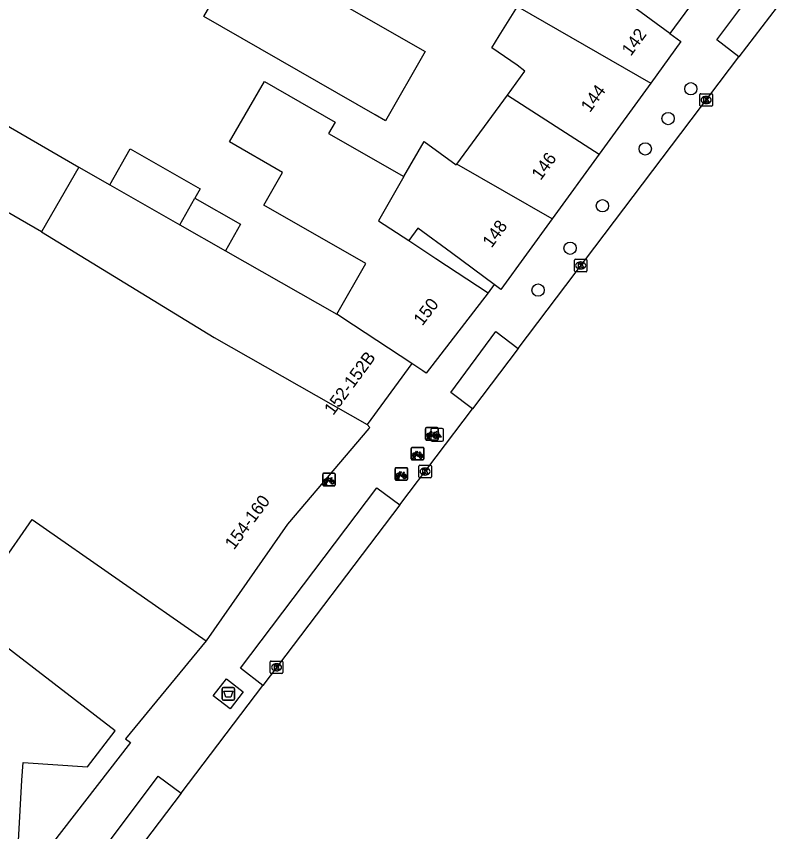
# Model space of a CAD drawing. Extents: x 160107 to 160928, y 382056 to 382918.
# Drawn here: x 160585.8 to 160647.1, y 382341.2 to 382406.2 of the extents above; entities that cross this region are included whole.
import ezdxf

# ---------------------------------------------------------------- set-up
doc = ezdxf.new("R2010")
doc.units = 0
for name, color, linetype in [('IMGEO_Afval_apart_plaats', 7, 'Continuous'), ('IMGEO_Boom', 7, 'Continuous'), ('IMGEO_Fietsenrek', 7, 'Continuous'), ('IMGEO_Kolk', 7, 'Continuous'), ('IMGEO_Lichtpunt', 7, 'Continuous'), ('IMGEO_Pand', 7, 'Continuous'), ('IMGEO_Pand_nummerreeks', 7, 'Continuous'), ('IMGEO_Rijbaan_lokaal_gesloten', 7, 'Continuous'), ('IMGEO_Voetpad_gesloten', 7, 'Continuous'), ('IMGEO_Voetpad_open', 7, 'Continuous')]:
    doc.layers.add(name, color=color, linetype=linetype)

msp = doc.modelspace()

# ---------------------------------------------------------------- linework, layer by layer
at = {"layer": 'IMGEO_Afval_apart_plaats'}
for p, q in [((160602.22, 382351.759), (160602.22, 382352.559)), ((160602.22, 382352.559), (160602.22, 382351.759)), ((160602.32, 382352.659), (160603.11, 382352.659)), ((160603.11, 382352.659), (160602.32, 382352.659)), ((160603.21, 382352.559), (160603.21, 382351.759)), ((160603.21, 382351.759), (160603.21, 382352.559)), ((160603.11, 382351.659), (160602.32, 382351.659)), ((160602.32, 382351.659), (160603.11, 382351.659))]:
    msp.add_line(p, q, dxfattribs=at)
msp.add_lwpolyline([(160602.363, 382352.373), (160603.067, 382352.373), (160602.918, 382351.903), (160602.512, 382351.903), (160602.363, 382352.373)], dxfattribs=at)
for centre, start, end in [((160602.32, 382352.559), 90, 180), ((160602.32, 382352.559), 90, 180), ((160603.11, 382352.559), 0, 90), ((160603.11, 382352.559), 360, 90), ((160602.32, 382351.759), 180, 270), ((160602.32, 382351.759), 180, 270), ((160603.11, 382351.759), 270, 0), ((160603.11, 382351.759), 270, 0)]:
    msp.add_arc(centre, 0.1, start, end, dxfattribs=at)
at = {"layer": 'IMGEO_Boom'}
for centre in [(160639.602, 382400.402), (160637.786, 382398.026), (160635.967, 382395.607), (160632.551, 382391.073), (160629.969, 382387.686), (160627.415, 382384.351)]:
    msp.add_circle(centre, 0.489, dxfattribs=at)
at = {"layer": 'IMGEO_Fietsenrek'}
for p, q in [((160618.447, 382372.462), (160618.447, 382373.303)), ((160618.447, 382373.303), (160618.447, 382372.462)), ((160618.522, 382373.387), (160619.363, 382373.387)), ((160619.363, 382373.387), (160618.522, 382373.387)), ((160619.447, 382373.312), (160619.447, 382372.471)), ((160619.447, 382372.471), (160619.447, 382373.312)), ((160618.574, 382372.471), (160618.613, 382372.631)), ((160618.685, 382372.643), (160618.684, 382372.647)), ((160618.716, 382372.654), (160618.717, 382372.647)), ((160619.134, 382372.936), (160619.17, 382372.841)), ((160619.372, 382372.387), (160618.531, 382372.387)), ((160618.531, 382372.387), (160619.372, 382372.387)), ((160618.608, 382372.471), (160618.574, 382372.471)), ((160618.643, 382372.619), (160618.608, 382372.471)), ((160618.726, 382372.471), (160618.692, 382372.613)), ((160618.724, 382372.617), (160618.759, 382372.471)), ((160618.759, 382372.471), (160618.726, 382372.471)), ((160617.303, 382370.886), (160617.303, 382371.727)), ((160617.303, 382371.727), (160617.303, 382370.886)), ((160617.378, 382371.811), (160618.219, 382371.811)), ((160618.219, 382371.811), (160617.378, 382371.811)), ((160617.99, 382371.36), (160618.026, 382371.265)), ((160618.303, 382371.736), (160618.303, 382370.895)), ((160618.303, 382370.895), (160618.303, 382371.736)), ((160618.228, 382370.811), (160617.387, 382370.811)), ((160617.387, 382370.811), (160618.228, 382370.811)), ((160617.43, 382370.895), (160617.469, 382371.055)), ((160617.464, 382370.895), (160617.43, 382370.895)), ((160617.499, 382371.043), (160617.464, 382370.895)), ((160617.541, 382371.067), (160617.54, 382371.071)), ((160617.582, 382370.895), (160617.548, 382371.037)), ((160617.572, 382371.078), (160617.573, 382371.071)), ((160617.58, 382371.041), (160617.615, 382370.895)), ((160617.615, 382370.895), (160617.582, 382370.895)), ((160616.008, 382369.266), (160616.008, 382370.107)), ((160616.008, 382370.107), (160616.008, 382369.266)), ((160616.083, 382370.191), (160616.924, 382370.191)), ((160616.924, 382370.191), (160616.083, 382370.191)), ((160617.008, 382370.116), (160617.008, 382369.275)), ((160617.008, 382369.275), (160617.008, 382370.116)), ((160610.242, 382368.821), (160610.242, 382369.662)), ((160610.242, 382369.662), (160610.242, 382368.821)), ((160610.317, 382369.746), (160611.158, 382369.746)), ((160611.158, 382369.746), (160610.317, 382369.746)), ((160611.242, 382369.671), (160611.242, 382368.83)), ((160611.242, 382368.83), (160611.242, 382369.671)), ((160616.135, 382369.275), (160616.174, 382369.435)), ((160616.204, 382369.423), (160616.169, 382369.275)), ((160616.246, 382369.447), (160616.245, 382369.451)), ((160616.287, 382369.275), (160616.253, 382369.417)), ((160616.277, 382369.458), (160616.278, 382369.451)), ((160616.285, 382369.421), (160616.32, 382369.275)), ((160616.695, 382369.74), (160616.731, 382369.645)), ((160611.167, 382368.746), (160610.326, 382368.746)), ((160610.326, 382368.746), (160611.167, 382368.746)), ((160610.369, 382368.83), (160610.408, 382368.99)), ((160610.403, 382368.83), (160610.369, 382368.83)), ((160610.438, 382368.978), (160610.403, 382368.83)), ((160610.48, 382369.002), (160610.479, 382369.006)), ((160610.521, 382368.83), (160610.487, 382368.972)), ((160610.511, 382369.013), (160610.512, 382369.006)), ((160610.519, 382368.976), (160610.554, 382368.83)), ((160610.554, 382368.83), (160610.521, 382368.83)), ((160610.929, 382369.295), (160610.965, 382369.2)), ((160616.933, 382369.191), (160616.092, 382369.191)), ((160616.092, 382369.191), (160616.933, 382369.191)), ((160616.169, 382369.275), (160616.135, 382369.275)), ((160616.32, 382369.275), (160616.287, 382369.275))]:
    msp.add_line(p, q, dxfattribs=at)
for points in [[(160618.781, 382372.861), (160618.729, 382372.771), (160618.689, 382372.746), (160618.69, 382372.793), (160618.745, 382372.887)], [(160618.76, 382372.913), (160618.855, 382373.077), (160618.941, 382373.063), (160618.943, 382373.054), (160618.887, 382373.043), (160618.86, 382372.998), (160619.116, 382372.957)], [(160619.056, 382372.669), (160619.006, 382372.669), (160618.815, 382372.92), (160618.796, 382372.888)], [(160619.103, 382372.932), (160618.846, 382372.973), (160618.829, 382372.944), (160618.996, 382372.724), (160619.103, 382372.932)], [(160619.151, 382372.834), (160619.121, 382372.911), (160619.012, 382372.693), (160619.055, 382372.693)], [(160619.085, 382372.693), (160619.205, 382372.692), (160619.161, 382372.806)], [(160619.181, 382372.813), (160619.236, 382372.668), (160619.086, 382372.668)], [(160619.116, 382372.957), (160619.141, 382373.006), (160619.135, 382373.01), (160619.112, 382373.014), (160619.1, 382373.021), (160619.099, 382373.024), (160619.101, 382373.029), (160619.196, 382373.014), (160619.198, 382373.004), (160619.188, 382372.991), (160619.176, 382372.985), (160619.162, 382372.991), (160619.134, 382372.936)], [(160617.616, 382371.337), (160617.711, 382371.501), (160617.797, 382371.487), (160617.799, 382371.478), (160617.743, 382371.467), (160617.716, 382371.422), (160617.972, 382371.381)], [(160617.912, 382371.093), (160617.862, 382371.093), (160617.671, 382371.344), (160617.652, 382371.312)], [(160617.959, 382371.356), (160617.702, 382371.397), (160617.685, 382371.368), (160617.852, 382371.148), (160617.959, 382371.356)], [(160618.007, 382371.258), (160617.977, 382371.335), (160617.868, 382371.117), (160617.911, 382371.117)], [(160617.972, 382371.381), (160617.997, 382371.43), (160617.991, 382371.434), (160617.968, 382371.438), (160617.956, 382371.445), (160617.955, 382371.448), (160617.957, 382371.453), (160618.052, 382371.438), (160618.054, 382371.428), (160618.044, 382371.415), (160618.032, 382371.409), (160618.018, 382371.415), (160617.99, 382371.36)], [(160617.637, 382371.285), (160617.585, 382371.195), (160617.545, 382371.17), (160617.546, 382371.217), (160617.601, 382371.311)], [(160617.941, 382371.117), (160618.061, 382371.116), (160618.017, 382371.23)], [(160618.037, 382371.237), (160618.092, 382371.092), (160617.942, 382371.092)], [(160610.555, 382369.272), (160610.65, 382369.436), (160610.736, 382369.422), (160610.738, 382369.413), (160610.682, 382369.402), (160610.655, 382369.357), (160610.911, 382369.316)], [(160610.911, 382369.316), (160610.936, 382369.365), (160610.93, 382369.369), (160610.907, 382369.373), (160610.895, 382369.38), (160610.894, 382369.383), (160610.896, 382369.388), (160610.991, 382369.373), (160610.993, 382369.363), (160610.983, 382369.35), (160610.971, 382369.344), (160610.957, 382369.35), (160610.929, 382369.295)], [(160616.342, 382369.665), (160616.29, 382369.575), (160616.25, 382369.55), (160616.251, 382369.597), (160616.306, 382369.691)], [(160616.321, 382369.717), (160616.416, 382369.881), (160616.502, 382369.867), (160616.504, 382369.858), (160616.448, 382369.847), (160616.421, 382369.802), (160616.677, 382369.761)], [(160616.617, 382369.473), (160616.567, 382369.473), (160616.376, 382369.724), (160616.357, 382369.692)], [(160616.664, 382369.736), (160616.407, 382369.777), (160616.39, 382369.748), (160616.557, 382369.528), (160616.664, 382369.736)], [(160616.712, 382369.638), (160616.682, 382369.715), (160616.573, 382369.497), (160616.616, 382369.497)], [(160616.646, 382369.497), (160616.766, 382369.496), (160616.722, 382369.61)], [(160616.742, 382369.617), (160616.797, 382369.472), (160616.647, 382369.472)], [(160616.677, 382369.761), (160616.702, 382369.81), (160616.696, 382369.814), (160616.673, 382369.818), (160616.661, 382369.825), (160616.66, 382369.828), (160616.662, 382369.833), (160616.757, 382369.818), (160616.759, 382369.808), (160616.749, 382369.795), (160616.737, 382369.789), (160616.723, 382369.795), (160616.695, 382369.74)], [(160610.576, 382369.22), (160610.524, 382369.13), (160610.484, 382369.105), (160610.485, 382369.152), (160610.54, 382369.246)], [(160610.851, 382369.028), (160610.801, 382369.028), (160610.61, 382369.279), (160610.591, 382369.247)], [(160610.898, 382369.291), (160610.641, 382369.332), (160610.624, 382369.303), (160610.791, 382369.083), (160610.898, 382369.291)], [(160610.946, 382369.193), (160610.916, 382369.27), (160610.807, 382369.052), (160610.85, 382369.052)], [(160610.88, 382369.052), (160611, 382369.051), (160610.956, 382369.165)], [(160610.976, 382369.172), (160611.031, 382369.027), (160610.881, 382369.027)]]:
    msp.add_lwpolyline(points, dxfattribs=at)
for centre, radius, start, end in [((160618.525, 382373.309), 0.0779, 92.4484, 184.28452), ((160618.525, 382373.309), 0.0779, 92.4484, 184.28452), ((160619.369, 382373.309), 0.0779, 2.4484, 94.28452), ((160619.369, 382373.309), 0.0779, 2.4484, 94.28452), ((160618.687, 382372.772), 0.159, 62.67661, 242.13685), ((160618.687, 382372.772), 0.129, 63.31916, 238.90302), ((160618.667, 382372.643), 0.0499, 12.8025, 158.69338), ((160618.667, 382372.643), 0.0174, 12.8025, 163.45023), ((160618.687, 382372.772), 0.129, 253.41502, 269.02044), ((160618.687, 382372.772), 0.129, 283.60429, 43.43025), ((160618.687, 382372.772), 0.159, 283.5766, 46.60424), ((160619.214, 382372.688), 0.159, 113.3408, 178.32165), ((160619.214, 382372.688), 0.159, 187.0065, 105.77075), ((160619.214, 382372.688), 0.129, 113.92302, 177.95563), ((160619.214, 382372.688), 0.129, 188.67146, 104.58832), ((160618.525, 382372.465), 0.0779, 182.4484, 274.28452), ((160618.525, 382372.465), 0.0779, 182.4484, 274.28452), ((160618.687, 382372.772), 0.159, 253.99666, 271.78671), ((160619.369, 382372.465), 0.0779, 272.4484, 4.28452), ((160619.369, 382372.465), 0.0779, 272.4484, 4.28452), ((160617.381, 382371.733), 0.0779, 92.4484, 184.28452), ((160617.381, 382371.733), 0.0779, 92.4484, 184.28452), ((160617.543, 382371.196), 0.159, 62.67661, 242.13685), ((160618.225, 382371.733), 0.0779, 2.4484, 94.28452), ((160618.225, 382371.733), 0.0779, 2.4484, 94.28452), ((160617.381, 382370.889), 0.0779, 182.4484, 274.28452), ((160617.381, 382370.889), 0.0779, 182.4484, 274.28452), ((160617.543, 382371.196), 0.129, 63.31916, 238.90302), ((160617.523, 382371.067), 0.0499, 12.8025, 158.69338), ((160617.543, 382371.196), 0.159, 253.99666, 271.78671), ((160617.523, 382371.067), 0.0174, 12.8025, 163.45023), ((160617.543, 382371.196), 0.129, 253.41502, 269.02044), ((160617.543, 382371.196), 0.129, 283.60429, 43.43025), ((160617.543, 382371.196), 0.159, 283.5766, 46.60424), ((160618.07, 382371.112), 0.159, 113.3408, 178.32165), ((160618.07, 382371.112), 0.159, 187.0065, 105.77075), ((160618.07, 382371.112), 0.129, 113.92302, 177.95563), ((160618.07, 382371.112), 0.129, 188.67146, 104.58832), ((160618.225, 382370.889), 0.0779, 272.4484, 4.28452), ((160618.225, 382370.889), 0.0779, 272.4484, 4.28452), ((160616.086, 382370.113), 0.0779, 92.4484, 184.28452), ((160616.086, 382370.113), 0.0779, 92.4484, 184.28452), ((160616.93, 382370.113), 0.0779, 2.4484, 94.28452), ((160616.93, 382370.113), 0.0779, 2.4484, 94.28452), ((160610.32, 382369.668), 0.0779, 92.4484, 184.28452), ((160610.32, 382369.668), 0.0779, 92.4484, 184.28452), ((160611.164, 382369.668), 0.0779, 2.4484, 94.28452), ((160611.164, 382369.668), 0.0779, 2.4484, 94.28452), ((160616.248, 382369.576), 0.159, 62.67661, 242.13685), ((160616.248, 382369.576), 0.129, 63.31916, 238.90302), ((160616.228, 382369.447), 0.0499, 12.8025, 158.69338), ((160616.248, 382369.576), 0.159, 253.99666, 271.78671), ((160616.228, 382369.447), 0.0174, 12.8025, 163.45023), ((160616.248, 382369.576), 0.129, 253.41502, 269.02044), ((160616.248, 382369.576), 0.129, 283.60429, 43.43025), ((160616.248, 382369.576), 0.159, 283.5766, 46.60424), ((160616.775, 382369.492), 0.159, 113.3408, 178.32165), ((160616.775, 382369.492), 0.159, 187.0065, 105.77075), ((160616.775, 382369.492), 0.129, 113.92302, 177.95563), ((160616.775, 382369.492), 0.129, 188.67146, 104.58832), ((160610.32, 382368.824), 0.0779, 182.4484, 274.28452), ((160610.32, 382368.824), 0.0779, 182.4484, 274.28452), ((160610.482, 382369.131), 0.159, 62.67661, 242.13685), ((160610.482, 382369.131), 0.129, 63.31916, 238.90302), ((160610.462, 382369.002), 0.0499, 12.8025, 158.69338), ((160610.482, 382369.131), 0.159, 253.99666, 271.78671), ((160610.462, 382369.002), 0.0174, 12.8025, 163.45023), ((160610.482, 382369.131), 0.129, 253.41502, 269.02044), ((160610.482, 382369.131), 0.129, 283.60429, 43.43025), ((160610.482, 382369.131), 0.159, 283.5766, 46.60424), ((160611.009, 382369.047), 0.159, 113.3408, 178.32165), ((160611.009, 382369.047), 0.159, 187.0065, 105.77075), ((160611.009, 382369.047), 0.129, 113.92302, 177.95563), ((160611.009, 382369.047), 0.129, 188.67146, 104.58832), ((160611.164, 382368.824), 0.0779, 272.4484, 4.28452), ((160611.164, 382368.824), 0.0779, 272.4484, 4.28452), ((160616.086, 382369.269), 0.0779, 182.4484, 274.28452), ((160616.086, 382369.269), 0.0779, 182.4484, 274.28452), ((160616.93, 382369.269), 0.0779, 272.4484, 4.28452), ((160616.93, 382369.269), 0.0779, 272.4484, 4.28452)]:
    msp.add_arc(centre, radius, start, end, dxfattribs=at)
at = {"layer": 'IMGEO_Kolk'}
for p, q in [((160640.323, 382399.083), (160640.323, 382399.935)), ((160640.398, 382400.009), (160641.25, 382400.009)), ((160641.324, 382399.935), (160641.324, 382399.083)), ((160640.811, 382399.789), (160640.836, 382399.789)), ((160641.25, 382399.009), (160640.398, 382399.009)), ((160640.834, 382399.229), (160640.809, 382399.229)), ((160630.315, 382385.891), (160630.315, 382386.743)), ((160630.39, 382386.817), (160631.242, 382386.817)), ((160630.803, 382386.597), (160630.828, 382386.597)), ((160631.316, 382386.743), (160631.316, 382385.891)), ((160631.242, 382385.817), (160630.39, 382385.817)), ((160630.826, 382386.037), (160630.801, 382386.037)), ((160617.905, 382369.458), (160617.905, 382370.31)), ((160617.98, 382370.384), (160618.832, 382370.384)), ((160618.393, 382370.164), (160618.418, 382370.164)), ((160618.906, 382370.31), (160618.906, 382369.458)), ((160618.832, 382369.384), (160617.98, 382369.384)), ((160618.416, 382369.604), (160618.391, 382369.604)), ((160606.064, 382353.852), (160606.064, 382354.704)), ((160606.139, 382354.778), (160606.991, 382354.778)), ((160606.552, 382354.558), (160606.577, 382354.558)), ((160607.065, 382354.704), (160607.065, 382353.852)), ((160606.991, 382353.778), (160606.139, 382353.778)), ((160606.575, 382353.998), (160606.55, 382353.998))]:
    msp.add_line(p, q, dxfattribs=at)
for points in [[(160640.323, 382399.083), (160640.323, 382399.935)], [(160640.398, 382400.009), (160641.25, 382400.009)], [(160641.324, 382399.935), (160641.324, 382399.083)], [(160640.644, 382399.709), (160640.767, 382399.709), (160640.767, 382399.558), (160640.897, 382399.709), (160641.061, 382399.709), (160640.915, 382399.558), (160641.068, 382399.309), (160640.916, 382399.309), (160640.831, 382399.473), (160640.767, 382399.406), (160640.767, 382399.309), (160640.644, 382399.309), (160640.644, 382399.709)], [(160641.25, 382399.009), (160640.398, 382399.009)], [(160630.315, 382385.891), (160630.315, 382386.743)], [(160630.39, 382386.817), (160631.242, 382386.817)], [(160630.636, 382386.517), (160630.759, 382386.517), (160630.759, 382386.366), (160630.889, 382386.517), (160631.053, 382386.517), (160630.907, 382386.366), (160631.06, 382386.117), (160630.908, 382386.117), (160630.823, 382386.281), (160630.759, 382386.214), (160630.759, 382386.117), (160630.636, 382386.117), (160630.636, 382386.517)], [(160631.316, 382386.743), (160631.316, 382385.891)], [(160631.242, 382385.817), (160630.39, 382385.817)], [(160617.905, 382369.458), (160617.905, 382370.31)], [(160617.98, 382370.384), (160618.832, 382370.384)], [(160618.226, 382370.084), (160618.349, 382370.084), (160618.349, 382369.933), (160618.479, 382370.084), (160618.643, 382370.084), (160618.497, 382369.933), (160618.65, 382369.684), (160618.498, 382369.684), (160618.413, 382369.848), (160618.349, 382369.781), (160618.349, 382369.684), (160618.226, 382369.684), (160618.226, 382370.084)], [(160618.906, 382370.31), (160618.906, 382369.458)], [(160618.832, 382369.384), (160617.98, 382369.384)], [(160606.064, 382353.852), (160606.064, 382354.704)], [(160606.139, 382354.778), (160606.991, 382354.778)], [(160606.385, 382354.478), (160606.508, 382354.478), (160606.508, 382354.327), (160606.638, 382354.478), (160606.802, 382354.478), (160606.656, 382354.327), (160606.809, 382354.078), (160606.657, 382354.078), (160606.572, 382354.242), (160606.508, 382354.175), (160606.508, 382354.078), (160606.385, 382354.078), (160606.385, 382354.478)], [(160607.065, 382354.704), (160607.065, 382353.852)], [(160606.991, 382353.778), (160606.139, 382353.778)]]:
    msp.add_lwpolyline(points, dxfattribs=at)
for centre, start, end in [((160640.4, 382399.933), 91.55205, 178.44795), ((160640.4, 382399.933), 91.55205, 178.44795), ((160641.248, 382399.933), 1.55205, 88.44795), ((160641.248, 382399.933), 1.55205, 88.44795), ((160640.4, 382399.085), 181.55205, 268.44795), ((160640.4, 382399.085), 181.55205, 268.44795), ((160641.248, 382399.085), 271.55205, 358.44795), ((160641.248, 382399.085), 271.55205, 358.44795), ((160630.392, 382386.741), 91.55205, 178.44795), ((160630.392, 382386.741), 91.55205, 178.44795), ((160631.24, 382386.741), 1.55205, 88.44795), ((160631.24, 382386.741), 1.55205, 88.44795), ((160630.392, 382385.893), 181.55205, 268.44795), ((160630.392, 382385.893), 181.55205, 268.44795), ((160631.24, 382385.893), 271.55205, 358.44795), ((160631.24, 382385.893), 271.55205, 358.44795), ((160617.982, 382370.308), 91.55205, 178.44795), ((160617.982, 382370.308), 91.55205, 178.44795), ((160618.83, 382370.308), 1.55205, 88.44795), ((160618.83, 382370.308), 1.55205, 88.44795), ((160617.982, 382369.46), 181.55205, 268.44795), ((160617.982, 382369.46), 181.55205, 268.44795), ((160618.83, 382369.46), 271.55205, 358.44795), ((160618.83, 382369.46), 271.55205, 358.44795), ((160606.141, 382354.702), 91.55205, 178.44795), ((160606.141, 382354.702), 91.55205, 178.44795), ((160606.989, 382354.702), 1.55205, 88.44795), ((160606.989, 382354.702), 1.55205, 88.44795), ((160606.141, 382353.854), 181.55205, 268.44795), ((160606.141, 382353.854), 181.55205, 268.44795), ((160606.989, 382353.854), 271.55205, 358.44795), ((160606.989, 382353.854), 271.55205, 358.44795)]:
    msp.add_arc(centre, 0.0765, start, end, dxfattribs=at)
for centre, major_axis, ratio, start_param, end_param in [((160640.81, 382399.509), (-0.387, 0.002), 0.722429, 4.712389, 7.853982), ((160640.835, 382399.509), (-0.39, 0.002), 0.717154, 1.570796, 4.712389), ((160630.802, 382386.317), (-0.387, 0.002), 0.722429, 4.712389, 7.853982), ((160630.827, 382386.317), (-0.39, 0.002), 0.717154, 1.570796, 4.712389), ((160618.392, 382369.884), (-0.387, 0.002), 0.722429, 4.712389, 7.853982), ((160618.417, 382369.884), (-0.39, 0.002), 0.717154, 1.570796, 4.712389), ((160606.551, 382354.278), (-0.387, 0.002), 0.722429, 4.712389, 7.853982), ((160606.576, 382354.278), (-0.39, 0.002), 0.717154, 1.570796, 4.712389)]:
    msp.add_ellipse(centre, major_axis=major_axis, ratio=ratio, start_param=start_param, end_param=end_param, dxfattribs=at)
at = {"layer": 'IMGEO_Lichtpunt'}
for p, q in [((160619.777, 382373.31), (160618.969, 382373.31)), ((160619.777, 382373.31), (160618.969, 382373.31)), ((160618.875, 382373.215), (160618.875, 382372.408)), ((160618.875, 382373.215), (160618.875, 382372.408)), ((160619.871, 382372.408), (160619.871, 382373.215)), ((160619.871, 382372.408), (160619.871, 382373.215)), ((160618.969, 382372.314), (160619.777, 382372.314)), ((160618.969, 382372.314), (160619.777, 382372.314))]:
    msp.add_line(p, q, dxfattribs=at)
for points in [[(160619.249, 382372.879), (160619.288, 382372.851), (160619.1, 382372.589), (160619.062, 382372.616), (160619.249, 382372.879)], [(160619.351, 382372.831), (160619.398, 382372.831), (160619.398, 382372.509), (160619.351, 382372.509), (160619.351, 382372.831)], [(160619.461, 382372.851), (160619.499, 382372.878), (160619.686, 382372.616), (160619.647, 382372.588), (160619.461, 382372.851)]]:
    msp.add_lwpolyline(points, dxfattribs=at)
msp.add_circle((160619.374, 382373.013), 0.0994, dxfattribs=at)
for centre, start, end in [((160618.969, 382373.215), 90, 180), ((160618.969, 382373.215), 90, 180), ((160619.777, 382373.215), 0, 90), ((160619.777, 382373.215), 0, 90), ((160618.969, 382372.408), 180, 270), ((160618.969, 382372.408), 180, 270), ((160619.777, 382372.408), 270, 0), ((160619.777, 382372.408), 270, 360)]:
    msp.add_arc(centre, 0.0946, start, end, dxfattribs=at)
at = {"layer": 'IMGEO_Pand'}
for points in [[(160603.933, 382411.678), (160618.421, 382403.365), (160615.257, 382397.851), (160614.438, 382398.321), (160600.769, 382406.163), (160603.933, 382411.678)], [(160637.926, 382404.821), (160631.971, 382409.192)], [(160640.769, 382408.693), (160637.926, 382404.821)], [(160624.966, 382399.89), (160626.373, 382401.805), (160625.763, 382402.294), (160623.729, 382403.674), (160624.326, 382404.628), (160625.785, 382406.959)], [(160625.785, 382406.959), (160636.404, 382400.85)], [(160637.926, 382404.821), (160638.813, 382404.168), (160636.404, 382400.85)], [(160576.566, 382395.495), (160579.551, 382400.655), (160590.805, 382394.145)], [(160611.357, 382382.44), (160613.67, 382386.463), (160605.547, 382391.136), (160607.041, 382393.732), (160602.817, 382396.162), (160605.592, 382400.986), (160611.23, 382397.743), (160610.716, 382396.85), (160616.716, 382393.4)], [(160636.404, 382400.85), (160632.294, 382395.191)], [(160620.927, 382394.392), (160624.966, 382399.89)], [(160624.966, 382399.89), (160632.294, 382395.191)], [(160616.716, 382393.4), (160618.334, 382396.212), (160620.887, 382394.337), (160620.927, 382394.392)], [(160587.82, 382388.985), (160576.566, 382395.495)], [(160593.259, 382392.747), (160594.893, 382395.616), (160600.477, 382392.436), (160600.052, 382391.69)], [(160632.294, 382395.191), (160628.55, 382390.035)], [(160590.805, 382394.145), (160587.82, 382388.985)], [(160590.805, 382394.145), (160593.259, 382392.747)], [(160628.55, 382390.035), (160620.927, 382394.392)], [(160616.716, 382393.4), (160614.693, 382389.883), (160617.098, 382388.299)], [(160593.259, 382392.747), (160598.843, 382389.567)], [(160598.843, 382389.567), (160600.052, 382391.69)], [(160600.052, 382391.69), (160603.696, 382389.615), (160602.487, 382387.492)], [(160598.843, 382389.567), (160602.487, 382387.492)], [(160628.55, 382390.035), (160624.456, 382384.398), (160623.926, 382384.792)], [(160587.82, 382388.985), (160601.579, 382380.565), (160613.777, 382373.634)], [(160623.926, 382384.792), (160620.508, 382387.332), (160617.831, 382389.298), (160617.098, 382388.299)], [(160617.098, 382388.299), (160619.253, 382386.879), (160623.428, 382384.128)], [(160602.487, 382387.492), (160611.357, 382382.44)], [(160623.428, 382384.128), (160618.505, 382377.731), (160618.229, 382377.913), (160617.345, 382378.496)], [(160617.345, 382378.496), (160612.688, 382381.562), (160611.357, 382382.44)], [(160617.345, 382378.496), (160613.777, 382373.634)], [(160613.777, 382373.634), (160614.005, 382373.39), (160613.933, 382373.305), (160607.426, 382365.685), (160600.944, 382356.385)], [(160569.791, 382371.203), (160576.716, 382367.513), (160576.608, 382367.311), (160584.473, 382362.344), (160587.063, 382366.06), (160600.944, 382356.385)], [(160587.757, 382339.068), (160585.979, 382340.453), (160586.26, 382345.268), (160586.342, 382346.677), (160591.48, 382346.353), (160593.688, 382349.22), (160585.586, 382355.449), (160583.507, 382357.047), (160581.575, 382357.12), (160580.676, 382340.81), (160571.49, 382341.378), (160571.897, 382347.942), (160569.6, 382348.084), (160569.194, 382341.52), (160556.703, 382342.293)]]:
    msp.add_lwpolyline(points, dxfattribs=at)
at = {"layer": 'IMGEO_Rijbaan_lokaal_gesloten'}
for points in [[(160647.085, 382407.756), (160643.431, 382402.943)], [(160625.82, 382379.701), (160643.431, 382402.943)], [(160625.82, 382379.701), (160622.186, 382374.89)], [(160616.392, 382367.23), (160622.186, 382374.89)], [(160616.392, 382367.23), (160605.47, 382352.836)], [(160598.954, 382344.247), (160605.47, 382352.836)], [(160598.954, 382344.247), (160587.679, 382329.372)]]:
    msp.add_lwpolyline(points, dxfattribs=at)
at = {"layer": 'IMGEO_Voetpad_gesloten'}
msp.add_lwpolyline([(160601.51, 382352.005), (160602.573, 382353.357), (160603.905, 382352.316), (160602.856, 382350.964), (160601.51, 382352.005)], dxfattribs=at)
at = {"layer": 'IMGEO_Voetpad_open'}
for points in [[(160643.431, 382402.943), (160641.662, 382404.316), (160645.261, 382409.125), (160647.085, 382407.756)], [(160623.926, 382384.792), (160623.428, 382384.128)], [(160622.186, 382374.89), (160620.454, 382376.198), (160624.049, 382381.048), (160625.82, 382379.701)], [(160605.47, 382352.836), (160603.689, 382354.206), (160614.552, 382368.59), (160616.392, 382367.23)], [(160600.944, 382356.385), (160594.519, 382348.582), (160594.916, 382348.277), (160587.757, 382339.068)], [(160587.679, 382329.372), (160585.95, 382330.695), (160597.132, 382345.592), (160598.954, 382344.247)]]:
    msp.add_lwpolyline(points, dxfattribs=at)

# ---------------------------------------------------------------- texts
at = {"layer": 'IMGEO_Pand_nummerreeks'}
for s, rotation, p in [('142', 54.01273, (160634.812, 382402.946)), ('144', 54.01273, (160631.553, 382398.459)), ('146', 54.0128, (160627.626, 382393.052)), ('148', 54.01273, (160623.71, 382387.659)), ('150', 52.41991, (160618.187, 382381.449)), ('152-152B', 53.72625, (160611.082, 382374.313)), ('154-160', 53.3481, (160603.164, 382363.59))]:
    msp.add_text(s, height=1, rotation=rotation, dxfattribs=at).set_placement(p)

doc.saveas('drawing.dxf')
